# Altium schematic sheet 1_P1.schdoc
size 307 x 218 mm; Symbol: Drawing-Symbol_A4; Device: Drawing-Symbol_A4; @Project Name: Asimov; @Page Count: 1; @Update Date: 2025-05-15; @Create Date: 2025-02-28; @Schematic Name: İzolasyon İzleme Cihazı; @Page No: 1; @Page Name: P1; Company: EasyEDA.com; Version: V1.0; Page Size: A4; @Create Time: 20:30:48; @Update Time: 17:18:32; Width: 1170; Height: 825; Region Start: 1; X Region Count: 6; Y Region Count: 4; Blade Width: 10; Title Block Position: 3; @Board Name: Izolasyon İzleme Cihazı
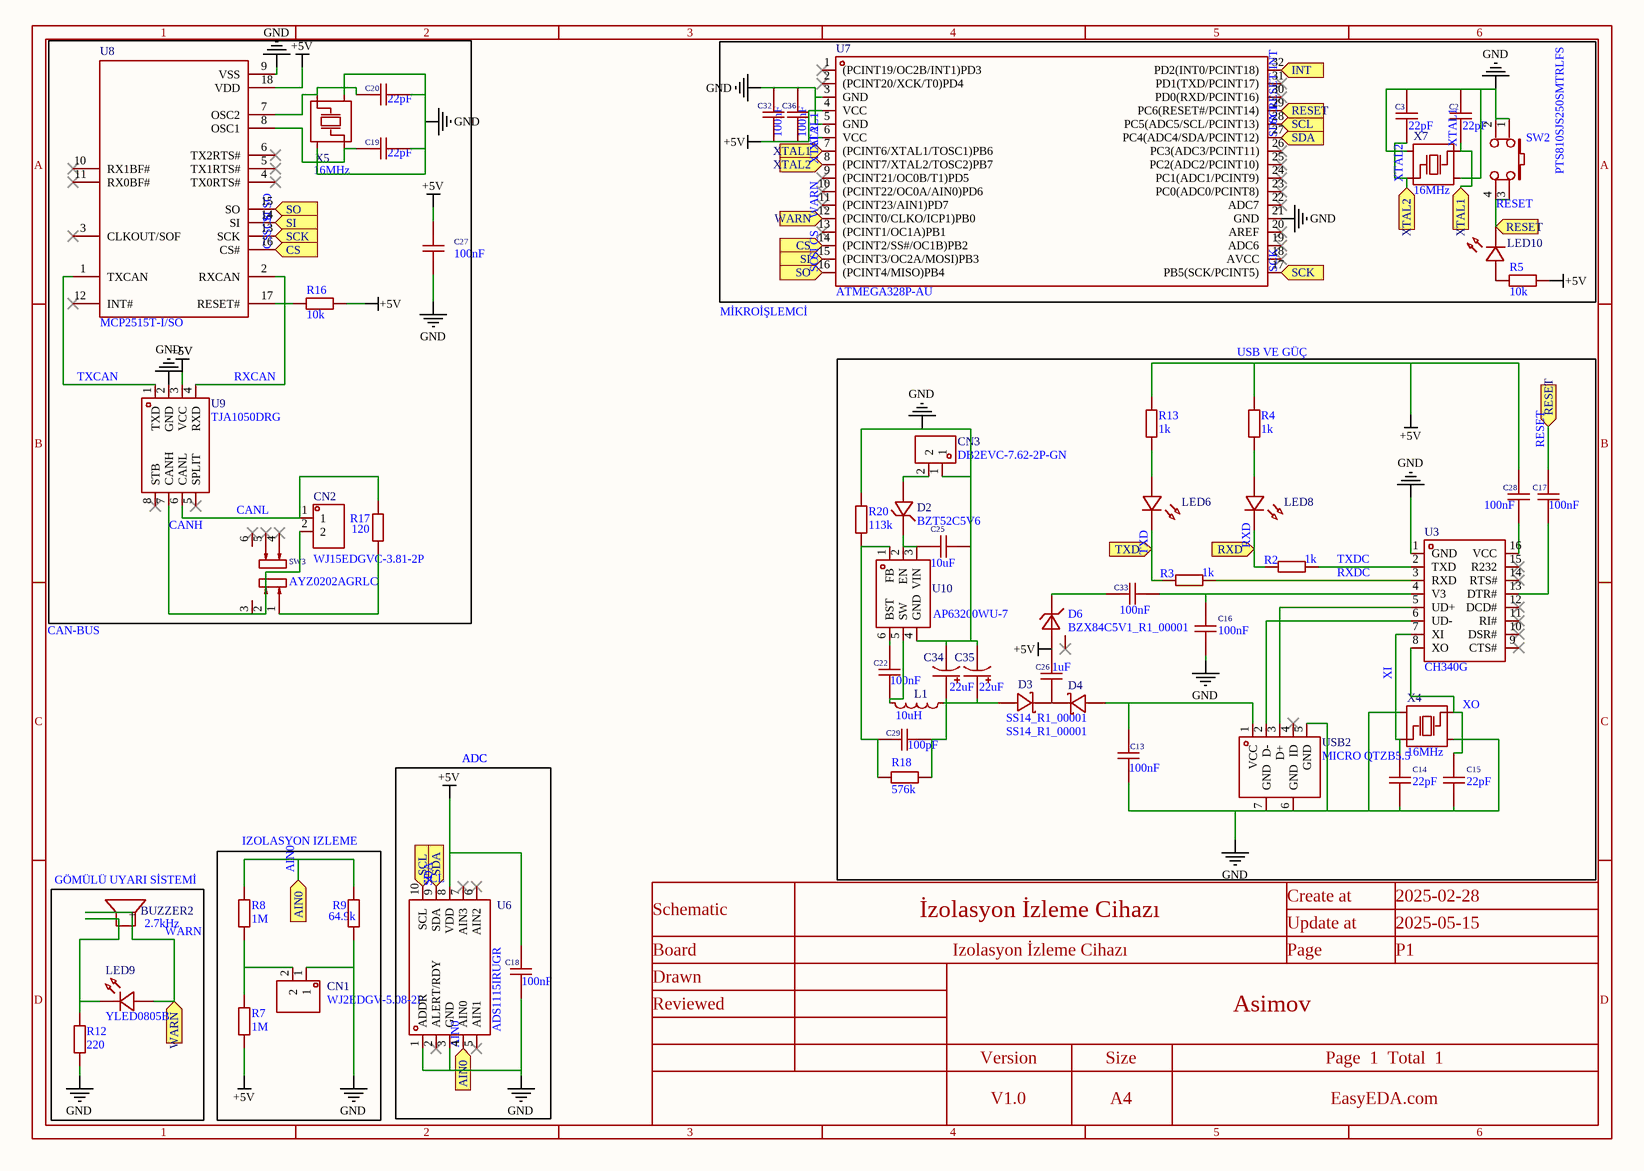
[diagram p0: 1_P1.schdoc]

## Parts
BUZZER2  2.7kHz  [BUZ-SMD_4P-L8.5-W8.5-P8.50-BR]
C2  22pF  [C0603]
C3  22pF  [C0603]
C13  100nF  [C0603]
C14  22pF  [C0603]
C15  22pF  [C0603]
C16  100nF  [C0603]
C17  100nF  [C0603]
C18  100nF  [C0603]
C19  22pF  [C0603]
C20  22pF  [C0603]
C22  100nF  [C0603]
C25  10uF  [C0603]
C26  1uF  [C0603]
C27  100nF  [C0603]
C28  100nF  [C0603]
C29  100pF  [C0603]
C32  100nF  [C0603]
C33  100nF  [C0603]
C34  22uF  [CAP-SMD_BD4.0-L4.3-W4.3-FD]
C35  22uF  [CAP-SMD_BD4.0-L4.3-W4.3-FD]
C36  100nF  [C0603]
CN1  WJ2EDGV-5.08-2P  [CONN-TH_WJ2EDGV-5.08-2P]
CN2  WJ15EDGVC-3.81-2P  [CONN-TH_WJ15EDGVC-3.81-2P]
CN3  DB2EVC-7.62-2P-GN  [CONN-TH_2P-P7.62_DB2EVC-7.62-2P]
D2  BZT52C5V6  [SOD-123_L2.8-W1.8-LS3.7-RD]
D3  SS14_R1_00001  [SMA_L4.4-W2.8-LS5.4-RD]
D4  SS14_R1_00001  [SMA_L4.4-W2.8-LS5.4-RD]
D6  BZX84C5V1_R1_00001  [SOT-23-3_L2.9-W1.3-P1.90-LS2.4-BR]
L1  10uH  [IND-SMD_L6.0-W6.0]
LED6  (no value)  [LED0402-RD_YELLOW]
LED8  (no value)  [LED0402-RD_YELLOW]
LED9  YLED0805B  [LED0805-RD]
LED10  (no value)  [LED0402-RD_YELLOW]
R2  1k  [R0603]
R3  1k  [R0603]
R4  1k  [R0603]
R5  10k  [R0603]
R7  1M  [R0603]
R8  1M  [R0603]
R9  64.9k  [R0603]
R12  220  [R0603]
R13  1k  [R0603]
R16  10k  [R0603]
R17  120  [R0603]
R18  576k  [R0603]
R20  113k  [R0603]
SW2  PTS810SJS250SMTRLFS  [SW-SMD_4P_PTS810SJM250SMTRLFS]
SW3  AYZ0202AGRLC  [SW-SMD_AYZ0202AGRLC]
U3  CH340G  [SOIC-16_L9.9-W3.9-P1.27-LS6.0-BL]
U6  ADS1115IRUGR  [X2QFN-10_L2.0-W1.5-P0.50-BL]
U7  ATMEGA328P-AU  [TQFP-32_L7.0-W7.0-P0.80-LS9.0-BL]
U8  MCP2515T-I/SO  [SOIC-18_L11.6-W7.5-P1.27-LS10.3-BL]
U9  TJA1050DRG  [SOP-8_L4.9-W3.9-P1.27-LS6.0-BL]
U10  AP63200WU-7  [SOT-23-6_L2.9-W1.6-P0.95-LS2.8-BR]
USB2  MICRO QTZB5.5  [MICRO-USB-SMD_MICRO-QTZB5.5]
X4  16MHz  [CRYSTAL-SMD_4P-L3.2-W2.5-BL]
X5  16MHz  [CRYSTAL-SMD_4P-L3.2-W2.5-BL]
X7  16MHz  [CRYSTAL-SMD_4P-L3.2-W2.5-BL]

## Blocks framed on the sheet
USB VE GÜÇ: C13-C17 C22 C25 C26 C28 C29 C33-C35 CN3 D2-D4 D6 L1 LED6 LED8 R2-R4 R13 R18 R20 U3 U10 USB2 X4
IZOLASYON IZLEME: CN1 R7-R9
GÖMÜLÜ UYARI SİSTEMİ: BUZZER2 LED9 R12

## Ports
AIN0 (in), CS (in), INT (in), RESET (in), RXD (in), SCK (in), SCL (in), SDA (in), SI (in), SO (in), TXD (in), WARN (in), XTAL1 (in), XTAL2 (in)

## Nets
+5V: C18.1 C26.2 C27.2 C28.2 C32.2 C36.2 D6.1(A) R4.2 R5.2 R7.1 R13.2 R16.1 U6.8(VDD) U7.4(VCC) U7.6(VCC) U8.18(VDD) U9.3(VCC)
GND: C2.2 C3.2 C13.1 C14.2 C15.2 C16.2 C18.2 C19.2 C20.2 C25.1 C27.1 C32.1 C34.2 C35.2 C36.1 CN1.1 CN3.1 R9.2 R12.1 R20.2 SW2.1 SW2.2 U3.1(GND) U6.1(ADDR) U6.3(GND) U7.3(GND) U7.5(GND) U7.21(GND) U8.9(VSS) U9.2(GND) U10.4(GND) USB2.5(GND) USB2.6(GND) USB2.7(GND) X4.2 X4.4 X5.2 X5.4 X7.2 X7.4
AIN0: R8.2 R9.1 U6.4(AIN0) ; port AIN0
CANH: CN2.2 SW3.2 SW3.3 U9.7(CANH)
CANL: CN2.1 R17.1 U9.6(CANL)
CS: U7.14((PCINT2/SS#/OC1B)PB2) U8.16(CS#) ; port CS
INT: U7.32(PD2(INT0/PCINT18)) ; port INT
RESET: C17.1 LED10.2(C) SW2.3 SW2.4 U7.29(PC6(RESET#/PCINT14)) ; port RESET
RXCAN: U8.2(RXCAN) U9.4(RXD)
RXD: LED8.2(C) R2.1 ; port RXD
RXDC: R3.2 U3.3(RXD)
SCK: U7.17(PB5(SCK/PCINT5)) U8.13(SCK) ; port SCK
SCL: U6.10(SCL) U7.28(PC5(ADC5/SCL/PCINT13)) ; port SCL
SDA: U6.9(SDA) U7.27(PC4(ADC4/SDA/PCINT12)) ; port SDA
SI: U7.15((PCINT3/OC2A/MOSI)PB3) U8.14(SI) ; port SI
SO: U7.16((PCINT4/MISO)PB4) U8.15(SO) ; port SO
TXCAN: U8.1(TXCAN) U9.1(TXD)
TXD: LED6.2(C) R3.1 ; port TXD
TXDC: R2.2 U3.2(TXD)
WARN: BUZZER2.1(+) BUZZER2.4 LED9.2(A) U7.12((PCINT0/CLKO/ICP1)PB0) ; port WARN
XI: C14.1 U3.7(XI) X4.1
XO: C15.1 U3.8(XO) X4.3
XTAL1: C2.1 U7.7((PCINT6/XTAL1/TOSC1)PB6) X7.3 ; port XTAL1
XTAL2: C3.1 U7.8((PCINT7/XTAL2/TOSC2)PB7) X7.1 ; port XTAL2
NetBUZZER2_2: BUZZER2.2 BUZZER2.3 LED9.1(K) R12.2
NetC13_2: C13.2 D4.2(A) USB2.1(VCC)
NetC16_1: C16.1 C33.1 U3.4(V3)
NetC17_2: C17.2 U3.13(DTR#)
NetC19_1: C19.1 U8.8(OSC1) X5.1
NetC20_1: C20.1 U8.7(OSC2) X5.3
NetC22_1: C22.1 L1.1 U10.5(SW)
NetC22_2: C22.2 U10.6(BST)
NetC25_2: C25.2 D2.1 U10.2(EN) U10.3(VIN)
NetC26_1: C26.1 D3.1(K) D4.1(K)
NetC28_1: C28.1 U3.16(VCC)
NetC29_1: C29.1 R18.1 R20.1 U10.1(FB)
NetC29_2: C29.2 C34.1 C35.1 D3.2(A) L1.2 R18.2
NetC33_2: C33.2 D6.3(C)
NetCN1_2: CN1.2 R7.2 R8.1
NetCN3_2: CN3.2 D2.2
NetLED6_1: LED6.1(A) R13.1
NetLED8_1: LED8.1(A) R4.1
NetLED10_1: LED10.1(A) R5.1
NetR16_2: R16.2 U8.17(RESET#)
NetR17_2: R17.2 SW3.1
NetU3_5: U3.5(UD+) USB2.3(D+)
NetU3_6: U3.6(UD-) USB2.2(D-)

Not connected (* = marked no-connect by the designer): D6 2*; SW3 4* 5* 6*; U3 9(CTS#)* 10(DSR#)* 11(RI#)* 12(DCD#)* 14(RTS#)* 15(R232)*; U6 2(ALERT/RDY)* 5(AIN1)* 6(AIN2)* 7(AIN3)*; U7 1((PCINT19/OC2B/INT1)PD3)* 2((PCINT20/XCK/T0)PD4)* 9((PCINT21/OC0B/T1)PD5)* 10((PCINT22/OC0A/AIN0)PD6)* 11((PCINT23/AIN1)PD7)* 13((PCINT1/OC1A)PB1)* 18(AVCC)* 19(ADC6)* 20(AREF)* 22(ADC7)* 23(PC0(ADC0/PCINT8))* 24(PC1(ADC1/PCINT9))* 25(PC2(ADC2/PCINT10))* 26(PC3(ADC3/PCINT11))* 30(PD0(RXD/PCINT16))* 31(PD1(TXD/PCINT17))*; U8 3(CLKOUT/SOF)* 4(TX0RTS#)* 5(TX1RTS#)* 6(TX2RTS#)* 10(RX1BF#)* 11(RX0BF#)* 12(INT#)*; U9 5(SPLIT)* 8(STB)*; USB2 4(ID)*

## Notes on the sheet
- MİKROİŞLEMCİ
- CAN-BUS
- ADC

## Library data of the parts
BUZZER2 = MLT-8530: Manufacturer: 华能; Add into BOM: yes; Driver Circuitry: Passive (external drive); Voltage - Supply: 2.5V~4.5V; Sound Pressure Level(SPL): 80dB
C2 C3 C14 C15 C19 C20 = FCC1206N220J102DT: Manufacturer: FOJAN(富捷); Add into BOM: yes; Tolerance: ±5%
C13 C16-C18 C22 C25-C29 C32 C33 C36 = CC0603KRX7R9BB104: Manufacturer: YAGEO(国巨); Add into BOM: yes; Tolerance: ±10%
C34 C35 = VT1H4R7M-CRC54: Manufacturer: VT(首科); Add into BOM: yes; Tolerance: ±20%; Lifetime @ Temp: 1000hrs@105℃
CN1 = WJ2EDGV-5.08-2P_C8461: Manufacturer: KANGNEX(康奈克斯电气); Add into BOM: yes; Connector Type: Board end/socket - Open type; Structure: 1x2P; Pitch: 5.08mm; Number of PINs Per Row: 2; Current Rating (Max): 20A; Voltage Rating (Max): 450V
CN2 = WJ15EDGVC-3.81-2P_C8396: Manufacturer: KANGNEX(康奈克斯电气); Add into BOM: yes; Connector Type: Receptacle-Close; Structure: 1x2P; Pitch: 3.81mm; Number of PINs Per Row: 2; Current Rating (Max): 8A; Voltage Rating (Max): 300V
CN3 = DB2EVC-7.62-2P-GN: Manufacturer: DORABO(地博电气); Add into BOM: yes; Connector Type: 板端/Receptacle-Close; Structure: 1x2P; Pitch: 7.62mm; Number of PINs Per Row: 2; Current Rating (Max): 20A; Voltage Rating (Max): 320V
D2 = BZT52C5V6_C173406: Manufacturer: MDD(辰达半导体); Add into BOM: yes; Diode Configuration: Independent Type; Zener Voltage(Nom): 5.6V; Reverse Leakage Current (Ir): 1uA@2.5V; Zener Voltage(Range): 5.2V~6V; Pd - Power Dissipation(Pd): 500mW; Impedance(Zzt): 80Ω
D3 D4 = SS14_R1_00001: Manufacturer: PANJIT(强茂); Symbol: SS14_C124751; Add into BOM: yes; Forward Voltage (Vf@If): 500mV@1A; Reverse Voltage (Vr): 40V; Rectified Current: 1A; Reverse Leakage Current (Ir): 200uA@40V
D6 = BZX84C5V1_R1_00001: Manufacturer: PANJIT(强茂); Add into BOM: yes; Zener Voltage (Nom): 5.1V; Reverse Leakage Current (Ir): 2uA@2V; Power Dissipation: 410mW; Zener Impedance (Zzt): 60Ω; Tolerance: ±5%
L1 = ASPI-0628-100M-T1: Manufacturer: ABRACON; Add into BOM: yes; Tolerance: ±20%
LED6 LED8 LED10 = LED_0402-R: Symbol: LED_R; Convert to PCB: yes
LED9 = YLED0805B: Manufacturer: YONGYUTAI(永裕泰); Add into BOM: yes; Emitted Color: Blue; Forward Voltage (VF): 2.7V~3.1V; Forward Current: 25mA; Dominant Wavelength: 457nm~475nm
R2-R4 R7-R9 R12 R13 R17 R18 R20 = Res_0603: Symbol: Res; Convert to PCB: yes; Value: 10K
R5 R16 = Res_0603: Symbol: Res; Convert to PCB: yes
SW2 = PTS810SJS250SMTRLFS: Manufacturer: C&K; Add into BOM: yes; Circuit: SPST; Actuator Style: Round Button; Operating Force: 600gf; Switch Length: 4.2mm; Switch Width: 3.2mm; Switch Height: 2.5mm; Contact Current: 50mA; Voltage Rating (DC): 16V; Pin Style: J pin
SW3 = AYZ0202AGRLC: Manufacturer: C&K; Add into BOM: yes; Circuit: DPDT; Actuator Style: Rectangular columnar; Pin Style: Solder Lug; Voltage Rating (DC): 12V
U3 = CH340G: Manufacturer: WCH(南京沁恒); Add into BOM: yes; Applications Function: USB to UART; Supply Voltage: 5V；3.3V; Data Rate: 2Mbps
U6 = ADS1115IRUGR: Manufacturer: TI(德州仪器); Add into BOM: yes
U7 = ATMEGA328P-AU_C14877: Manufacturer: MICROCHIP(美国微芯); Add into BOM: yes; CPU Core: AVR; Program Storage Size: 32KB; RAM Size: 2KB; GPIO Ports Number: 23; Operating Voltage Range: 1.8V~5.5V; CPU Maximum Speed: 20MHz; Program Memory Type: FLASH; EEPROM: 1KB; ADC (Bit): 10bit; Peripheral/Function: WDT；PWM；WDT；PWM; Watchdog: 有
U8 = MCP2515T-I/SO: Manufacturer: MICROCHIP(美国微芯); Add into BOM: yes; Data Rate: 1Mbps; Supply Current: 5mA; Supply Voltage(Vcc): 2.7V~5.5V
U9 = TJA1050DRG: Manufacturer: HGC(深圳汉芯); Add into BOM: yes
U10 = AP63200WU-7: Manufacturer: DIODES(美台); Add into BOM: yes; Function: Step-down type; Output Type: Adjustable; Input Voltage: 3.8V~32V; Output Current: 2A; Switching Frequency: 500kHz; Number of Outputs: 1; Topology: Step-down; Quiescent Current (Iq): 22uA; Switch tube (built-in/external): Built-in
USB2 = MICRO QTZB5.5: Manufacturer: SHOU HAN(首韩); Add into BOM: yes; Connector Type: Micro-B; Gender: Female; Number of Contacts: 5P; Number of Ports: 1; Current Rating - Power (Max): 0.5A; Core Colour: Black
X4 X5 X7 = TAXM8M4RDBCCT2T: Manufacturer: YJX(雅晶鑫); Add into BOM: yes; Normal temperature Frequency Tolerance: ±10ppm; Frequency Stability: ±15ppm; Equivalent Series Resistance(ESR): 250Ω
